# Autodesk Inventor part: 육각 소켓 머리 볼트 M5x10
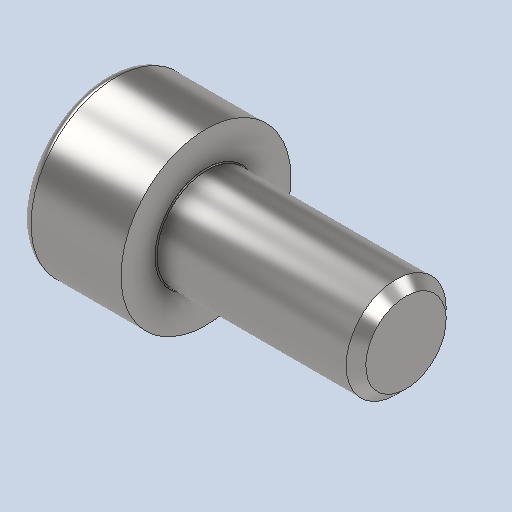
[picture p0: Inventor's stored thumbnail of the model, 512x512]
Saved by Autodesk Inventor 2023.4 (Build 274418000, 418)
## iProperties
Created: 2024-09
Part Number: 육각 소켓 머리 볼트 M5x10
Material: 강철, 연강
Description: 6각머리 태핑 나사
Document SubType Name: Modeling
Designer: 11
Density: 7.85 g/cm^3
Appearance: 기본값
Author: jhkim
Sending System: Autodesk Inventor 2025
Preprocessor: ST-DEVELOPER v20
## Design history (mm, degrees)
node "육각 소켓 머리 볼트 M5x101"
node "솔리드1"
body "Solid1"
